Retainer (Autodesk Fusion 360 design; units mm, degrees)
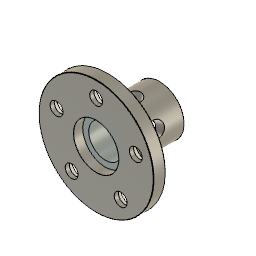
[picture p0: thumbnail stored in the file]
sketch "Sketch1" plane through (0, 0, 0) normal (1, 0, 0) x axis (0, 1, 0)
  line L1 (0, 8.7376) -> (0, 22.225)
  line L2 (3.556, 8.7376) -> (0, 8.7376)
  line L3 (3.556, 6.4389) -> (3.556, 8.7376)
  line L4 (24.638, 6.4389) -> (3.556, 6.4389)
  line L5 (24.638, 9.525) -> (24.638, 6.4389)
  line L6 (4.7625, 9.525) -> (24.638, 9.525)
  line L7 (4.7625, 22.225) -> (4.7625, 9.525)
  line L8 (0, 22.225) -> (4.7625, 22.225)
  line L9 (24.13, 9.144) -> (24.13, 9.525)
  line L10 (22.13, 9.144) -> (24.13, 9.144)
  line L11 (22.13, 9.525) -> (22.13, 9.144)
  point P1 (0, 0)
  point P3 (0, 8.7376)
  point P10 (24.13, 9.525)
  point P13 (22.13, 9.525)
  point P2 (0, 22.225)
  point P9 (4.7625, 22.225)
  point P4 (3.556, 8.7376)
  point P7 (24.638, 9.525)
  point P11 (24.13, 9.144)
  point P12 (22.13, 9.144)
  vertical L1
  perpendicular L1 L2
  perpendicular L2 L3
  perpendicular L3 L4
  perpendicular L4 L5
  perpendicular L5 L6
  perpendicular L6 L7
  perpendicular L1 L8
  vertical P1 P3
  coincident L6 P10
  perpendicular L6 L9
  perpendicular L5 L10
  coincident L6 P13
  perpendicular L6 L11
  dimension "d1" distance P2 P9 = 4.7625
  dimension "d2" distance P1 L4 = 6.4389 (= "( ( 0.5 + 0.006 + 0.001 ) / 2 ) * 1 in")
  dimension "d3" distance P1 L2 = 8.7376 (= "( ( 0.5 + 0.187 + 0.001 ) / 2 ) * 1 in")
  dimension "d4" distance P3 P4 = 3.556
  dimension "d5" distance P1 L8 = 22.225 (= "( 1.75 / 2 ) * 1 in")
  dimension "d6" distance P2 P7 = 24.638
  dimension "d7" distance P1 L6 = 9.525
  dimension "d45" distance P11 P12 = 2
  dimension "d46" distance P1 L10 = 9.144 (= "( 0.72 / 2 ) * 1 in")
  dimension "d47" distance L5 L9 = 0.508
revolve "Revolve1" sketch "Sketch1" AlongAngle 360
sketch "Sketch2" plane through (0, 0, 0) normal (1, 0, 0) x axis (0, 1, 0)
  line L1 (12.0759, 6.4389) -> (11.5318, 9.525)
  line L2 (4.7625, 9.525) -> (24.638, 9.525)
  line L3 (24.638, 6.4389) -> (3.556, 6.4389)
  line L4 (14.4189, 6.4389) -> (14.4189, 9.525)
  line L5 (12.2478, 5.4642) -> (11.5318, 9.525)
  line L6 (14.4189, 5.4642) -> (12.2478, 5.4642)
  line L7 (14.4189, 6.4389) -> (14.4189, 5.4642)
  line L8 (14.4189, 9.525) -> (17.306, 9.525)
  line L9 (16.59, 5.4642) -> (17.306, 9.525)
  line L10 (14.4189, 5.4642) -> (16.59, 5.4642)
  circle C1 centre (14.4189, 6.8644) radius 2.3813
  point P2 (11.5318, 9.525)
  point P3 (12.0759, 6.4389)
  point P8 (14.4189, 9.525)
  point P9 (14.4189, 6.4389)
  point P12 (17.306, 9.525)
  point P13 (14.4189, 9.525)
  point P10 (12.2478, 5.4642)
  point P14 (16.59, 5.4642)
  point P11 (14.4189, 5.4642)
  point P15 (14.4189, 5.4642)
  point P16 (14.4189, 6.8644)
  coincident P2 L2
  coincident P3 L3
  coincident L2 P8
  coincident L3 P9
  vertical L4
  parallel L1 L5
  perpendicular L4 L6
  perpendicular L3 L7
  symmetric P2 L4 P12
  symmetric P8 L4 P13
  symmetric L4 P10 P14
  symmetric L4 P11 P15
  coincident L4 P16
  tangent L5 C1
  dimension "d27" angle L1 L2 = 80
  dimension "d33" diameter C1 = 4.7625 (= "( 3 / 16 ) * 1 in")
  dimension "d44" distance P13 P16 = 2.6606 (= "( 0.1875 / 2 ) * 1 in + 0.011 in")
revolve "Revolve2" sketch "Sketch2" AlongAngle 360
circular_pattern "C-Pattern1" TotalAngle 360
sketch "Sketch4" plane through (0, 4.7625, 0) normal (0, 1, 0) x axis (-1, 0, 0)
  circle C1 centre (0, 16.129) radius 2.4892
  circle C2 centre (0, 0) radius 22.225
  circle C3 centre (0, 0) radius 9.525
  point P2 (0, 0)
  point P3 (0, 16.129)
  vertical P2 P3
  dimension "d18" diameter C1 = 4.9784
  dimension "d19" distance P2 P3 = 16.129
hole "Hole1" HoleDepth 5.08 HoleDiameter 4.9784 TipAngle 118 CSDiameter 10.4394 CSAngle 82
circular_pattern "C-Pattern2" TotalAngle 360
fillet "Fillet2" radius 0.127
fillet "Fillet3" radius 0.254
chamfer "Chamfer4" distance 0.127
chamfer "Chamfer5" distance 0.0254
fillet "Fillet4" radius 1.016
sketch "Sketch5" plane through (0, 3.556, 0) normal (0, -1, 0) x axis (1, 0, 0)
  circle C1 centre (0, 0) radius 6.4389
  circle C2 centre (0, 0) radius 8.7376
